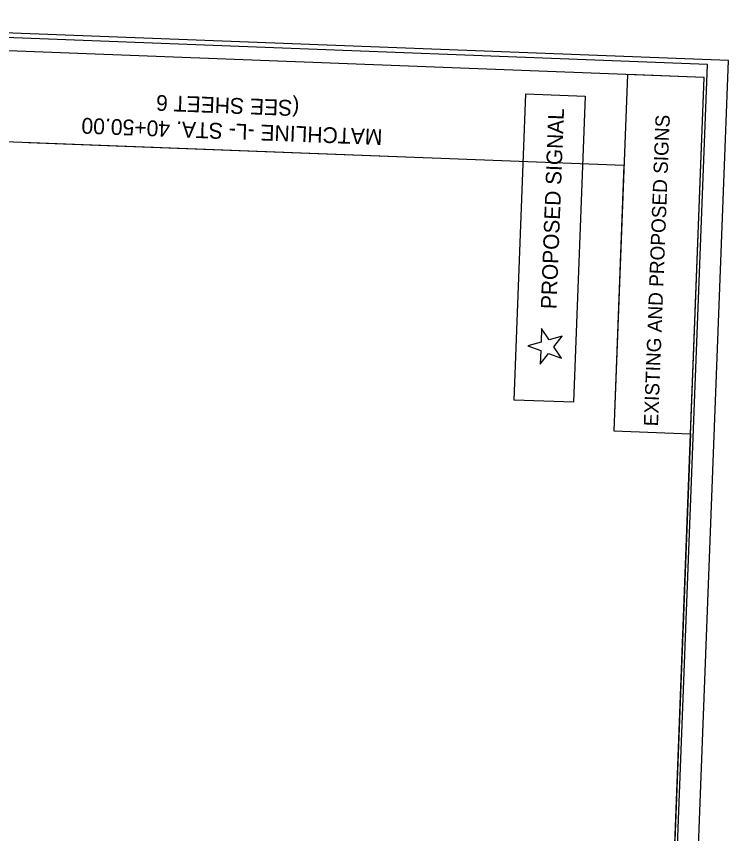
# Model space of a CAD drawing. Extents: x 2093420 to 2100301, y 676254 to 688367.
# Drawn here: x 2097581 to 2098257, y 687418 to 688194 of the extents above; entities that cross this region are included whole.
import ezdxf

# ---------------------------------------------------------------- set-up
doc = ezdxf.new("R2010")
doc.units = 0
for name, color, linetype in [('Default', 7, 'Continuous'), ('Matchline', 7, 'Continuous'), ('Matchline Text', 7, 'Continuous'), ('Old_Level_10', 7, 'Continuous'), ('Scratch_Level_0', 7, 'Continuous'), ('Scratch_Level_2', 7, 'Continuous'), ('Sheet Layout Plan Border', 7, 'Continuous'), ('Sheet Plan CELL', 7, 'Continuous'), ('Sheet Plot Border Inside CELL', 7, 'Continuous'), ('Sheet Plot Border Outside CELL', 7, 'Continuous')]:
    doc.layers.add(name, color=color, linetype=linetype)

msp = doc.modelspace()

# ---------------------------------------------------------------- linework, layer by layer
at = {"layer": 'Default'}
msp.add_lwpolyline([(2098053.62, 687830.02), (2098064.77, 688120.69), (2098121.27, 688118.53), (2098110.12, 687827.85)], close=True, dxfattribs=at)
msp.add_lwpolyline([(2098079.01, 687876.9), (2098078.52, 687863.99), (2098086.5, 687874.15), (2098098.65, 687869.68), (2098091.45, 687880.44), (2098099.44, 687890.61), (2098087, 687887.08), (2098079.81, 687897.82), (2098079.31, 687884.9), (2098066.86, 687881.37), (2098079.01, 687876.9)], dxfattribs=at)
at = {"layer": 'Matchline'}
msp.add_line((2097592.68, 688074.63), (2097942.42, 688061.22), dxfattribs=at)
at = {"layer": 'Old_Level_10'}
msp.add_lwpolyline([(2098221.08, 687797.91), (2098234.06, 688136.14), (2098161.28, 688138.94), (2098148.3, 687800.71)], close=True, dxfattribs=at)
msp.add_lwpolyline([(2098221.08, 687797.91), (2098234.06, 688136.14), (2098161.28, 688138.94), (2098148.3, 687800.71)], close=True, dxfattribs=at)
at = {"layer": 'Scratch_Level_0'}
msp.add_line((2098176.77, 686637.22), (2098221.12, 687797.91), dxfattribs=at)
at = {"layer": 'Scratch_Level_2'}
msp.add_lwpolyline([(2098179.19, 686705.44), (2097129.59, 686735.95), (2097169.5, 687776.57), (2097177.9, 687989.79), (2097203.71, 687988.8), (2097408.56, 687980.94), (2097412.42, 688081.55), (2098157.98, 688052.95), (2098148.3, 687800.71), (2098221.09, 687797.91)], close=True, dxfattribs=at)
at = {"layer": 'Sheet Layout Plan Border'}
msp.add_lwpolyline([(2098179.19, 686705.44), (2097129.59, 686735.95), (2097169.5, 687776.57), (2097177.9, 687989.79), (2097203.71, 687988.8), (2097408.56, 687980.94), (2097412.42, 688081.55), (2098157.98, 688052.95), (2098148.3, 687800.71), (2098221.09, 687797.91)], close=True, dxfattribs=at)
at = {"layer": 'Sheet Plan CELL'}
msp.add_lwpolyline([(2097185.06, 688176.42), (2097127.55, 686677.48), (2098176.77, 686637.22), (2098234.29, 688136.13)], close=True, dxfattribs=at)
msp.add_lwpolyline([(2097185.06, 688176.42), (2097127.55, 686677.48), (2098176.77, 686637.22), (2098234.29, 688136.13)], close=True, dxfattribs=at)
at = {"layer": 'Sheet Plot Border Inside CELL'}
msp.add_lwpolyline([(2098173.4, 686483.75), (2098237.27, 688148.52), (2097183.06, 688188.98), (2097119.17, 686524.21)], close=True, dxfattribs=at)
msp.add_lwpolyline([(2098173.4, 686483.75), (2098237.27, 688148.52), (2097183.06, 688188.98), (2097119.17, 686524.21)], close=True, dxfattribs=at)
at = {"layer": 'Sheet Plot Border Outside CELL'}
msp.add_lwpolyline([(2098192.89, 686470), (2098257.44, 688152.26), (2097163.24, 688194.24), (2097098.69, 686511.98)], close=True, dxfattribs=at)
msp.add_lwpolyline([(2098192.89, 686470), (2098257.44, 688152.26), (2097163.24, 688194.24), (2097098.69, 686511.98)], close=True, dxfattribs=at)

# ---------------------------------------------------------------- texts
at = {"layer": 'Default'}
for s, height, rotation, p in [('PROPOSED SIGNAL', 14.8414, 87.8037, (2098093.89, 687916.1)), ('EXISTING AND PROPOSED SIGNS', 13.5, 87.80253, (2098190.31, 687804.9))]:
    msp.add_text(s, height=height, rotation=rotation, dxfattribs=at).set_placement(p)
at = {"layer": 'Matchline Text'}
for s, p in [('(SEE SHEET 6', (2097850.02, 688114.46)), ('MATCHLINE -L- STA. 40+50.00', (2097928.97, 688087.04))]:
    msp.add_text(s, height=15, rotation=177.8037, dxfattribs=at).set_placement(p)

doc.saveas('drawing.dxf')
